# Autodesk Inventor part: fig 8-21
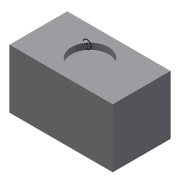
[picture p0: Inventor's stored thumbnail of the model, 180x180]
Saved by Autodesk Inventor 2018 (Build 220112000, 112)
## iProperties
Created: 2011-07
Part Number: fig 8-21
Material: Generic
Document SubType Name: Modeling
Designer: CadCim
Density: 1 g/cm^3
Appearance: Default
Author: CadCim
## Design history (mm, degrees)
sketch "Sketch1"
  geometry: L1 (-18, 10)-(7, 10); L2 (7, 10)-(7, -4); L3 (7, -4)-(-18, -4); L4 (-18, -4)-(-18, 10); 1 further point
  constraints: 8 end point, 2 parallel, 1 horizontal, 1 perpendicular
extrude "Extrusion1" new body sketch "Sketch1" distance "d0" = 14.25; taper "d1" = 0 deg
sketch "Sketch2"
  geometry: C1 r 4.5 at (-5.5, 3); 1 further point
  constraints: 1 centre point
extrude "Extrusion2" cut sketch "Sketch2" distance "d2" = 1.5; taper "d3" = 0 deg
workplane "Work Plane2"
sketch "Sketch4"
  geometry: C1 r 1 at (9, -14); 1 further point
  constraints: 1 centre point
body "Solid1"
other parameters: "d4" = -4.25
